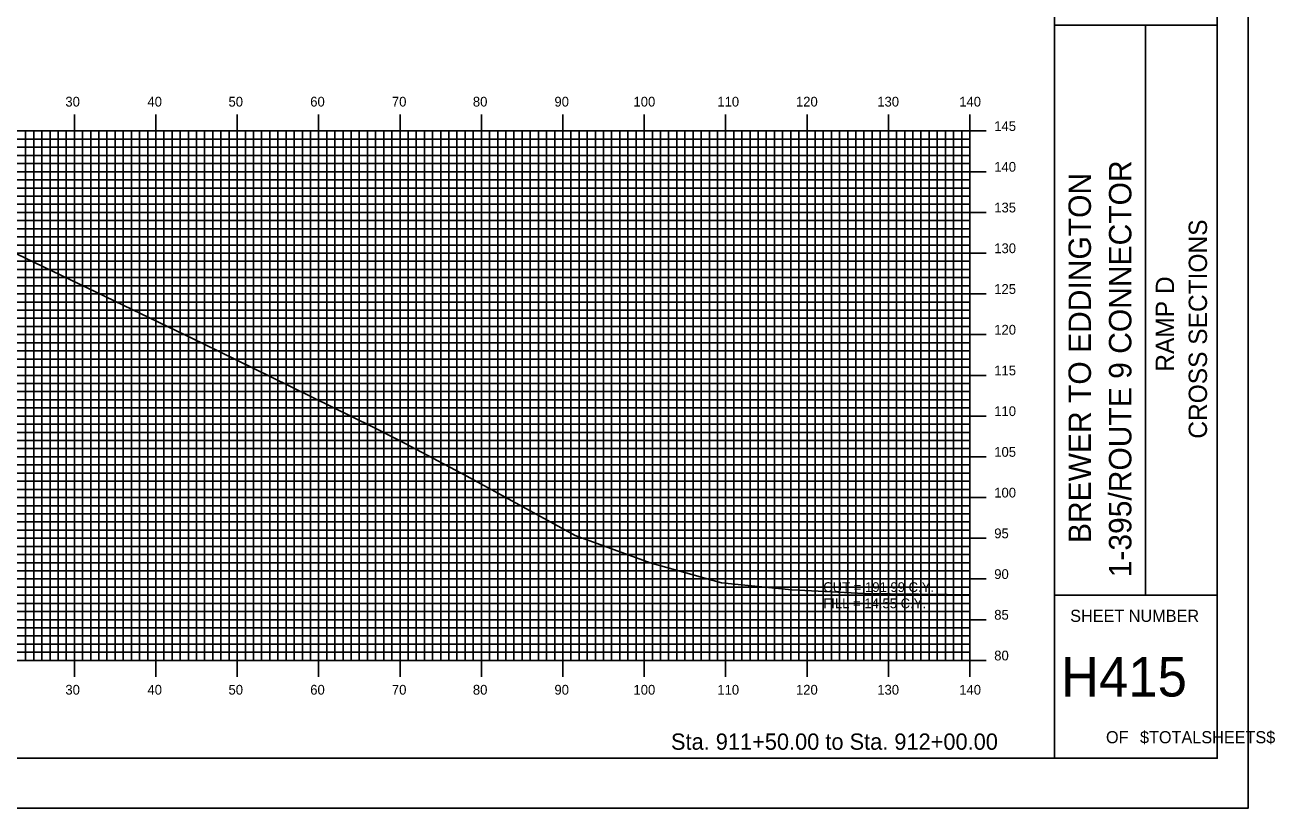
# Model space of a CAD drawing. Extents: x 859865 to 860208, y 364765 to 364985.
# Drawn here: x 860054.3 to 860207.9, y 364765.2 to 364861.3 of the extents above; entities that cross this region are included whole.
import ezdxf

# ---------------------------------------------------------------- set-up
doc = ezdxf.new("R2010")
doc.units = 0
for name, color, linetype in [('BORDER', 7, 'Continuous'), ('D_Text_Standard', 7, 'Continuous'), ('H_V ANNOTATION', 7, 'Continuous'), ('MAJOR', 7, 'Continuous'), ('MINOR', 7, 'Continuous'), ('PLOT BOUNDARY', 7, 'Continuous'), ('S_Roadway_Centerline', 7, 'Continuous')]:
    doc.layers.add(name, color=color, linetype=linetype)

msp = doc.modelspace()

# ---------------------------------------------------------------- linework, layer by layer
at = {"layer": 'BORDER'}
for p, q in [((860180.79, 364771.3), (860180.79, 364981.3)), ((860180.79, 364861.31), (860200.79, 364861.31)), ((860191.97, 364791.31), (860191.97, 364861.31)), ((860180.79, 364791.31), (860200.79, 364791.31))]:
    msp.add_line(p, q, dxfattribs=at)
msp.add_lwpolyline([(859880.79, 364771.3), (860200.79, 364771.3), (860200.79, 364981.3), (859880.79, 364981.3)], close=True, dxfattribs=at)
at = {"layer": 'MAJOR'}
for p, q in [((860060.39, 364850.31), (860060.39, 364848.3)), ((860070.39, 364850.31), (860070.39, 364848.3)), ((860080.39, 364850.31), (860080.39, 364848.3)), ((860090.39, 364850.31), (860090.39, 364848.3)), ((860100.39, 364850.31), (860100.39, 364848.3)), ((860110.39, 364850.31), (860110.39, 364848.3)), ((860120.39, 364850.31), (860120.39, 364848.3)), ((860130.39, 364850.31), (860130.39, 364848.3)), ((860140.39, 364850.31), (860140.39, 364848.3)), ((860150.39, 364850.31), (860150.39, 364848.3)), ((860160.39, 364850.31), (860160.39, 364848.3)), ((860170.39, 364850.31), (860170.39, 364848.3)), ((859890.39, 364848.3), (860170.39, 364848.3)), ((859890.39, 364848.3), (860170.39, 364848.3)), ((860060.39, 364783.3), (860060.39, 364848.3)), ((860070.39, 364783.3), (860070.39, 364848.3)), ((860080.39, 364783.3), (860080.39, 364848.3)), ((860090.39, 364783.3), (860090.39, 364848.3)), ((860100.39, 364783.3), (860100.39, 364848.3)), ((860110.39, 364783.3), (860110.39, 364848.3)), ((860120.39, 364783.3), (860120.39, 364848.3)), ((860130.39, 364783.3), (860130.39, 364848.3)), ((860140.39, 364783.3), (860140.39, 364848.3)), ((860150.39, 364783.3), (860150.39, 364848.3)), ((860160.39, 364783.3), (860160.39, 364848.3)), ((860172.39, 364848.3), (860168.38, 364848.3)), ((860170.39, 364783.3), (860170.39, 364848.3)), ((860170.39, 364783.3), (860170.39, 364848.3)), ((859890.39, 364843.3), (860170.39, 364843.3)), ((860172.39, 364843.3), (860168.38, 364843.3)), ((859890.39, 364838.3), (860170.39, 364838.3)), ((860172.39, 364838.3), (860168.38, 364838.3)), ((859890.39, 364833.3), (860170.39, 364833.3)), ((860172.39, 364833.3), (860168.38, 364833.3)), ((859890.39, 364828.3), (860170.39, 364828.3)), ((860172.39, 364828.3), (860168.38, 364828.3)), ((859890.39, 364823.3), (860170.39, 364823.3)), ((860172.39, 364823.3), (860168.38, 364823.3)), ((859890.39, 364818.3), (860170.39, 364818.3)), ((860172.39, 364818.3), (860168.38, 364818.3)), ((859890.39, 364813.3), (860170.39, 364813.3)), ((860172.39, 364813.3), (860168.38, 364813.3)), ((859890.39, 364808.3), (860170.39, 364808.3)), ((860172.39, 364808.3), (860168.38, 364808.3)), ((859890.39, 364803.3), (860170.39, 364803.3)), ((860172.39, 364803.3), (860168.38, 364803.3)), ((859890.39, 364798.3), (860170.39, 364798.3)), ((860172.39, 364798.3), (860168.38, 364798.3)), ((859890.39, 364793.3), (860170.39, 364793.3)), ((860172.39, 364793.3), (860168.38, 364793.3)), ((859890.39, 364788.3), (860170.39, 364788.3)), ((860172.39, 364788.3), (860168.38, 364788.3)), ((859890.39, 364783.3), (860170.39, 364783.3)), ((859890.39, 364783.3), (860170.39, 364783.3)), ((860060.39, 364781.3), (860060.39, 364783.3)), ((860070.39, 364781.3), (860070.39, 364783.3)), ((860080.39, 364781.3), (860080.39, 364783.3)), ((860090.39, 364781.3), (860090.39, 364783.3)), ((860100.39, 364781.3), (860100.39, 364783.3)), ((860110.39, 364781.3), (860110.39, 364783.3)), ((860120.39, 364781.3), (860120.39, 364783.3)), ((860130.39, 364781.3), (860130.39, 364783.3)), ((860140.39, 364781.3), (860140.39, 364783.3)), ((860150.39, 364781.3), (860150.39, 364783.3)), ((860160.39, 364781.3), (860160.39, 364783.3)), ((860172.39, 364783.3), (860168.38, 364783.3)), ((860170.39, 364781.3), (860170.39, 364783.3))]:
    msp.add_line(p, q, dxfattribs=at)
at = {"layer": 'MINOR'}
for p, q in [((859890.39, 364847.3), (860170.39, 364847.3)), ((860054.39, 364783.3), (860054.39, 364848.3)), ((860055.39, 364783.3), (860055.39, 364848.3)), ((860056.39, 364783.3), (860056.39, 364848.3)), ((860057.39, 364783.3), (860057.39, 364848.3)), ((860058.39, 364783.3), (860058.39, 364848.3)), ((860059.39, 364783.3), (860059.39, 364848.3)), ((860061.39, 364783.3), (860061.39, 364848.3)), ((860062.39, 364783.3), (860062.39, 364848.3)), ((860063.39, 364783.3), (860063.39, 364848.3)), ((860064.39, 364783.3), (860064.39, 364848.3)), ((860065.39, 364783.3), (860065.39, 364848.3)), ((860066.39, 364783.3), (860066.39, 364848.3)), ((860067.39, 364783.3), (860067.39, 364848.3)), ((860068.39, 364783.3), (860068.39, 364848.3)), ((860069.39, 364783.3), (860069.39, 364848.3)), ((860071.39, 364783.3), (860071.39, 364848.3)), ((860072.39, 364783.3), (860072.39, 364848.3)), ((860073.39, 364783.3), (860073.39, 364848.3)), ((860074.39, 364783.3), (860074.39, 364848.3)), ((860075.39, 364783.3), (860075.39, 364848.3)), ((860076.39, 364783.3), (860076.39, 364848.3)), ((860077.39, 364783.3), (860077.39, 364848.3)), ((860078.39, 364783.3), (860078.39, 364848.3)), ((860079.39, 364783.3), (860079.39, 364848.3)), ((860081.39, 364783.3), (860081.39, 364848.3)), ((860082.39, 364783.3), (860082.39, 364848.3)), ((860083.39, 364783.3), (860083.39, 364848.3)), ((860084.39, 364783.3), (860084.39, 364848.3)), ((860085.39, 364783.3), (860085.39, 364848.3)), ((860086.39, 364783.3), (860086.39, 364848.3)), ((860087.39, 364783.3), (860087.39, 364848.3)), ((860088.39, 364783.3), (860088.39, 364848.3)), ((860089.39, 364783.3), (860089.39, 364848.3)), ((860091.39, 364783.3), (860091.39, 364848.3)), ((860092.39, 364783.3), (860092.39, 364848.3)), ((860093.39, 364783.3), (860093.39, 364848.3)), ((860094.39, 364783.3), (860094.39, 364848.3)), ((860095.39, 364783.3), (860095.39, 364848.3)), ((860096.39, 364783.3), (860096.39, 364848.3)), ((860097.39, 364783.3), (860097.39, 364848.3)), ((860098.39, 364783.3), (860098.39, 364848.3)), ((860099.39, 364783.3), (860099.39, 364848.3)), ((860101.39, 364783.3), (860101.39, 364848.3)), ((860102.39, 364783.3), (860102.39, 364848.3)), ((860103.39, 364783.3), (860103.39, 364848.3)), ((860104.39, 364783.3), (860104.39, 364848.3)), ((860105.39, 364783.3), (860105.39, 364848.3)), ((860106.39, 364783.3), (860106.39, 364848.3)), ((860107.39, 364783.3), (860107.39, 364848.3)), ((860108.39, 364783.3), (860108.39, 364848.3)), ((860109.39, 364783.3), (860109.39, 364848.3)), ((860111.39, 364783.3), (860111.39, 364848.3)), ((860112.39, 364783.3), (860112.39, 364848.3)), ((860113.39, 364783.3), (860113.39, 364848.3)), ((860114.39, 364783.3), (860114.39, 364848.3)), ((860115.39, 364783.3), (860115.39, 364848.3)), ((860116.39, 364783.3), (860116.39, 364848.3)), ((860117.39, 364783.3), (860117.39, 364848.3)), ((860118.39, 364783.3), (860118.39, 364848.3)), ((860119.39, 364783.3), (860119.39, 364848.3)), ((860121.39, 364783.3), (860121.39, 364848.3)), ((860122.39, 364783.3), (860122.39, 364848.3)), ((860123.39, 364783.3), (860123.39, 364848.3)), ((860124.39, 364783.3), (860124.39, 364848.3)), ((860125.39, 364783.3), (860125.39, 364848.3)), ((860126.39, 364783.3), (860126.39, 364848.3)), ((860127.39, 364783.3), (860127.39, 364848.3)), ((860128.39, 364783.3), (860128.39, 364848.3)), ((860129.39, 364783.3), (860129.39, 364848.3)), ((860131.39, 364783.3), (860131.39, 364848.3)), ((860132.39, 364783.3), (860132.39, 364848.3)), ((860133.39, 364783.3), (860133.39, 364848.3)), ((860134.39, 364783.3), (860134.39, 364848.3)), ((860135.39, 364783.3), (860135.39, 364848.3)), ((860136.39, 364783.3), (860136.39, 364848.3)), ((860137.39, 364783.3), (860137.39, 364848.3)), ((860138.39, 364783.3), (860138.39, 364848.3)), ((860139.39, 364783.3), (860139.39, 364848.3)), ((860141.39, 364783.3), (860141.39, 364848.3)), ((860142.39, 364783.3), (860142.39, 364848.3)), ((860143.39, 364783.3), (860143.39, 364848.3)), ((860144.39, 364783.3), (860144.39, 364848.3)), ((860145.39, 364783.3), (860145.39, 364848.3)), ((860146.39, 364783.3), (860146.39, 364848.3)), ((860147.39, 364783.3), (860147.39, 364848.3)), ((860148.39, 364783.3), (860148.39, 364848.3)), ((860149.39, 364783.3), (860149.39, 364848.3)), ((860151.39, 364783.3), (860151.39, 364848.3)), ((860152.39, 364783.3), (860152.39, 364848.3)), ((860153.39, 364783.3), (860153.39, 364848.3)), ((860154.39, 364783.3), (860154.39, 364848.3)), ((860155.39, 364783.3), (860155.39, 364848.3)), ((860156.39, 364783.3), (860156.39, 364848.3)), ((860157.39, 364783.3), (860157.39, 364848.3)), ((860158.39, 364783.3), (860158.39, 364848.3)), ((860159.39, 364783.3), (860159.39, 364848.3)), ((860161.39, 364783.3), (860161.39, 364848.3)), ((860162.39, 364783.3), (860162.39, 364848.3)), ((860163.39, 364783.3), (860163.39, 364848.3)), ((860164.39, 364783.3), (860164.39, 364848.3)), ((860165.39, 364783.3), (860165.39, 364848.3)), ((860166.39, 364783.3), (860166.39, 364848.3)), ((860167.39, 364783.3), (860167.39, 364848.3)), ((860170.39, 364847.3), (860168.38, 364847.3)), ((860168.39, 364783.3), (860168.39, 364848.3)), ((860169.39, 364783.3), (860169.39, 364848.3)), ((859890.39, 364846.3), (860170.39, 364846.3)), ((860170.39, 364846.3), (860168.38, 364846.3)), ((859890.39, 364845.3), (860170.39, 364845.3)), ((859890.39, 364844.3), (860170.39, 364844.3)), ((860170.39, 364845.3), (860168.38, 364845.3)), ((860170.39, 364844.3), (860168.38, 364844.3)), ((859890.39, 364842.3), (860170.39, 364842.3)), ((859890.39, 364841.3), (860170.39, 364841.3)), ((860170.39, 364842.3), (860168.38, 364842.3)), ((860170.39, 364841.3), (860168.38, 364841.3)), ((859890.39, 364840.3), (860170.39, 364840.3)), ((860170.39, 364840.3), (860168.38, 364840.3)), ((859890.39, 364839.3), (860170.39, 364839.3)), ((860170.39, 364839.3), (860168.38, 364839.3)), ((859890.39, 364837.3), (860170.39, 364837.3)), ((860170.39, 364837.3), (860168.38, 364837.3)), ((859890.39, 364836.3), (860170.39, 364836.3)), ((859890.39, 364835.3), (860170.39, 364835.3)), ((860170.39, 364836.3), (860168.38, 364836.3)), ((860170.39, 364835.3), (860168.38, 364835.3)), ((859890.39, 364834.3), (860170.39, 364834.3)), ((860170.39, 364834.3), (860168.38, 364834.3)), ((859890.39, 364832.3), (860170.39, 364832.3)), ((860170.39, 364832.3), (860168.38, 364832.3)), ((859890.39, 364831.3), (860170.39, 364831.3)), ((859890.39, 364830.3), (860170.39, 364830.3)), ((860170.39, 364831.3), (860168.38, 364831.3)), ((860170.39, 364830.3), (860168.38, 364830.3)), ((859890.39, 364829.3), (860170.39, 364829.3)), ((860170.39, 364829.3), (860168.38, 364829.3)), ((859890.39, 364827.3), (860170.39, 364827.3)), ((860170.39, 364827.3), (860168.38, 364827.3)), ((859890.39, 364826.3), (860170.39, 364826.3)), ((860170.39, 364826.3), (860168.38, 364826.3)), ((859890.39, 364825.3), (860170.39, 364825.3)), ((859890.39, 364824.3), (860170.39, 364824.3)), ((860170.39, 364825.3), (860168.38, 364825.3)), ((860170.39, 364824.3), (860168.38, 364824.3)), ((859890.39, 364822.3), (860170.39, 364822.3)), ((859890.39, 364821.3), (860170.39, 364821.3)), ((860170.39, 364822.3), (860168.38, 364822.3)), ((860170.39, 364821.3), (860168.38, 364821.3)), ((859890.39, 364820.3), (860170.39, 364820.3)), ((860170.39, 364820.3), (860168.38, 364820.3)), ((859890.39, 364819.3), (860170.39, 364819.3)), ((860170.39, 364819.3), (860168.38, 364819.3)), ((859890.39, 364817.3), (860170.39, 364817.3)), ((860170.39, 364817.3), (860168.38, 364817.3)), ((859890.39, 364816.3), (860170.39, 364816.3)), ((859890.39, 364815.3), (860170.39, 364815.3)), ((860170.39, 364816.3), (860168.38, 364816.3)), ((860170.39, 364815.3), (860168.38, 364815.3)), ((859890.39, 364814.3), (860170.39, 364814.3)), ((860170.39, 364814.3), (860168.38, 364814.3)), ((859890.39, 364812.3), (860170.39, 364812.3)), ((860170.39, 364812.3), (860168.38, 364812.3)), ((859890.39, 364811.3), (860170.39, 364811.3)), ((860170.39, 364811.3), (860168.38, 364811.3)), ((859890.39, 364810.3), (860170.39, 364810.3)), ((859890.39, 364809.3), (860170.39, 364809.3)), ((860170.39, 364810.3), (860168.38, 364810.3)), ((860170.39, 364809.3), (860168.38, 364809.3)), ((859890.39, 364807.3), (860170.39, 364807.3)), ((860170.39, 364807.3), (860168.38, 364807.3)), ((859890.39, 364806.3), (860170.39, 364806.3)), ((860170.39, 364806.3), (860168.38, 364806.3)), ((859890.39, 364805.3), (860170.39, 364805.3)), ((859890.39, 364804.3), (860170.39, 364804.3)), ((860170.39, 364805.3), (860168.38, 364805.3)), ((860170.39, 364804.3), (860168.38, 364804.3)), ((859890.39, 364802.3), (860170.39, 364802.3)), ((859890.39, 364801.3), (860170.39, 364801.3)), ((860170.39, 364802.3), (860168.38, 364802.3)), ((860170.39, 364801.3), (860168.38, 364801.3)), ((859890.39, 364800.3), (860170.39, 364800.3)), ((860170.39, 364800.3), (860168.38, 364800.3)), ((859890.39, 364799.3), (860170.39, 364799.3)), ((860170.39, 364799.3), (860168.38, 364799.3)), ((859890.39, 364797.3), (860170.39, 364797.3)), ((860170.39, 364797.3), (860168.38, 364797.3)), ((859890.39, 364796.3), (860170.39, 364796.3)), ((859890.39, 364795.3), (860170.39, 364795.3)), ((860170.39, 364796.3), (860168.38, 364796.3)), ((860170.39, 364795.3), (860168.38, 364795.3)), ((859890.39, 364794.3), (860170.39, 364794.3)), ((860170.39, 364794.3), (860168.38, 364794.3)), ((859890.39, 364792.3), (860170.39, 364792.3)), ((860170.39, 364792.3), (860168.38, 364792.3)), ((859890.39, 364791.3), (860170.39, 364791.3)), ((860170.39, 364791.3), (860168.38, 364791.3)), ((859890.39, 364790.3), (860170.39, 364790.3)), ((859890.39, 364789.3), (860170.39, 364789.3)), ((860170.39, 364790.3), (860168.38, 364790.3)), ((860170.39, 364789.3), (860168.38, 364789.3)), ((859890.39, 364787.3), (860170.39, 364787.3)), ((860170.39, 364787.3), (860168.38, 364787.3)), ((859890.39, 364786.3), (860170.39, 364786.3)), ((860170.39, 364786.3), (860168.38, 364786.3)), ((859890.39, 364785.3), (860170.39, 364785.3)), ((859890.39, 364784.3), (860170.39, 364784.3)), ((860170.39, 364785.3), (860168.38, 364785.3)), ((860170.39, 364784.3), (860168.38, 364784.3))]:
    msp.add_line(p, q, dxfattribs=at)
at = {"layer": 'PLOT BOUNDARY'}
msp.add_lwpolyline([(859864.6, 364765.18), (860204.6, 364765.18), (860204.6, 364985.18), (859864.6, 364985.18)], close=True, dxfattribs=at)
at = {"layer": 'S_Roadway_Centerline'}
msp.add_lwpolyline([(860049.99, 364834.79), (860076.16, 364822.23), (860084.59, 364818.06), (860097.02, 364811.98), (860100.24, 364810.34), (860108.58, 364805.93), (860121.89, 364798.64), (860131.14, 364795.3), (860139.9, 364792.83), (860148.52, 364791.97), (860157.42, 364791.51), (860160.62, 364791.47), (860167.61, 364791.38), (860170.39, 364791.37)], dxfattribs=at)

# ---------------------------------------------------------------- texts
at = {"layer": 'BORDER'}
for s, height, p in [('1-395/ROUTE 9 CONNECTOR', 2.7557, (860190.24, 364793.5)), ('BREWER TO EDDINGTON', 2.7557, (860185.27, 364797.71)), ('CROSS SECTIONS', 2.25, (860199.53, 364810.52)), ('RAMP D', 2.25, (860195.48, 364818.75))]:
    msp.add_text(s, height=height, rotation=90, dxfattribs=at).set_placement(p)
for s, height, p in [('SHEET NUMBER', 1.4905, (860182.72, 364788.03)), ('H415', 4.839, (860181.59, 364778.87)), ('OF', 1.491, (860187.12, 364773.13)), ('$TOTALSHEETS$', 1.4905, (860191.3, 364773.13))]:
    msp.add_text(s, height=height, dxfattribs=at).set_placement(p)
at = {"layer": 'D_Text_Standard'}
for s, p in [('CUT = 191.99 C.Y.', (860152.39, 364791.7)), ('FILL = 14.55 C.Y.', (860152.39, 364789.71))]:
    msp.add_text(s, height=1.2, dxfattribs=at).set_placement(p)
at = {"layer": 'H_V ANNOTATION'}
for s, height, p in [('30', 1.2, (860059.28, 364851.3)), ('40', 1.2, (860069.36, 364851.3)), ('50', 1.2, (860079.32, 364851.3)), ('60', 1.2, (860089.36, 364851.3)), ('70', 1.2, (860099.39, 364851.3)), ('80', 1.2, (860109.34, 364851.3)), ('90', 1.2, (860119.36, 364851.3)), ('100', 1.2, (860129.07, 364851.3)), ('110', 1.2, (860139.37, 364851.3)), ('120', 1.2, (860149.03, 364851.3)), ('130', 1.2, (860159.02, 364851.3)), ('140', 1.2, (860169.09, 364851.3)), ('145', 1.2, (860173.39, 364848.3)), ('140', 1.2, (860173.39, 364843.3)), ('135', 1.2, (860173.39, 364838.3)), ('130', 1.2, (860173.39, 364833.3)), ('125', 1.2, (860173.39, 364828.3)), ('120', 1.2, (860173.39, 364823.3)), ('115', 1.2, (860173.39, 364818.3)), ('110', 1.2, (860173.39, 364813.3)), ('105', 1.2, (860173.39, 364808.3)), ('100', 1.2, (860173.39, 364803.3)), ('95', 1.2, (860173.39, 364798.3)), ('90', 1.2, (860173.39, 364793.3)), ('85', 1.2, (860173.39, 364788.3)), ('80', 1.2, (860173.39, 364783.3)), ('30', 1.2, (860059.28, 364779.1)), ('40', 1.2, (860069.36, 364779.1)), ('50', 1.2, (860079.32, 364779.1)), ('60', 1.2, (860089.36, 364779.1)), ('70', 1.2, (860099.39, 364779.1)), ('80', 1.2, (860109.34, 364779.1)), ('90', 1.2, (860119.36, 364779.1)), ('100', 1.2, (860129.07, 364779.1)), ('110', 1.2, (860139.37, 364779.1)), ('120', 1.2, (860149.03, 364779.1)), ('130', 1.2, (860159.02, 364779.1)), ('140', 1.2, (860169.09, 364779.1)), ('Sta. 911+50.00 to Sta. 912+00.00', 2.0004, (860133.68, 364772.33))]:
    msp.add_text(s, height=height, dxfattribs=at).set_placement(p)

doc.saveas('drawing.dxf')
